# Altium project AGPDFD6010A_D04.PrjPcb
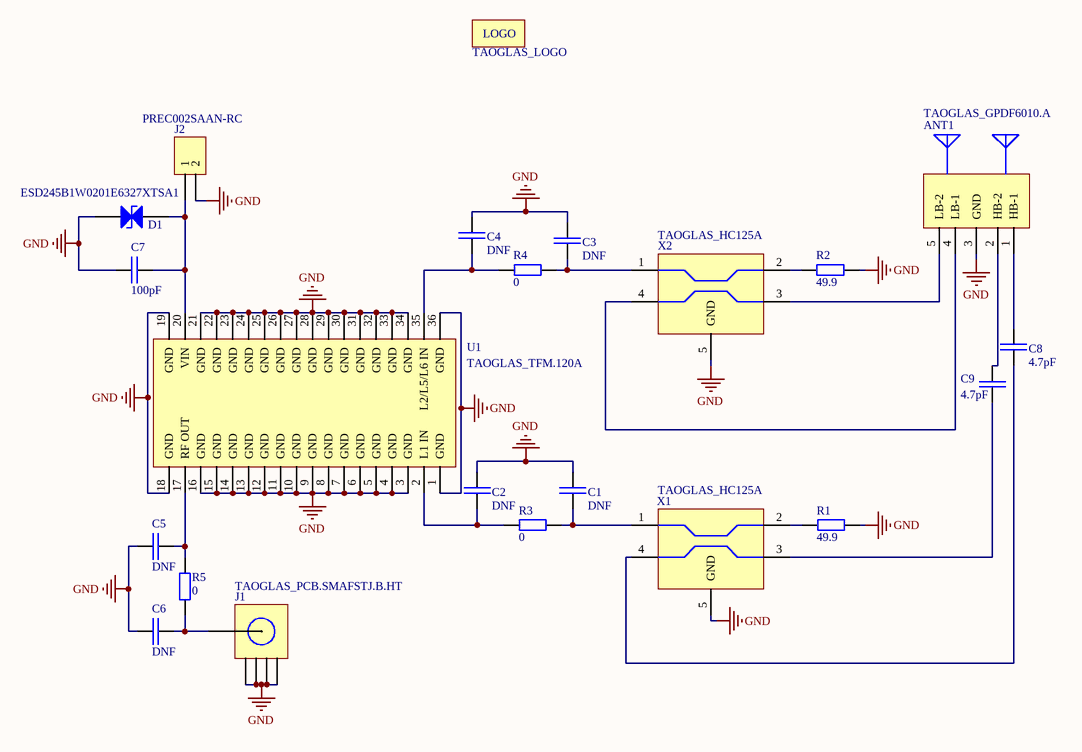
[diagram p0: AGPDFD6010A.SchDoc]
1 sheet, 22 parts. Net scope: global (net labels, ports and power ports of the same name join across sheets).
Board file: AGPDFD6010A_D04.PcbDoc

## Sheet AGPDFD6010A.SchDoc
size Tabloid; SheetNumber: 1; SheetTotal: 1; ProjName: AGPDFD6010A_D04.PrjPcb

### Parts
ANT1  TAOGLAS_GPDF6010.A  [TAOGLAS_GPDF6010.A]
C1  DNF  [0402 - DNF]
C2  DNF  [0402 - DNF]
C3  DNF  [0402 - DNF]
C4  DNF  [0402 - DNF]
C5  DNF  [0402 - DNF]
C6  DNF  [0402 - DNF]
C7  100pF  [Capacitor - 0402 - GRM]
C8  4.7pF  [Capacitor - 0402 - GRM]
C9  4.7pF  [Capacitor - 0402 - GRM]
D1  ESD245B1W0201E6327XTSA1  [Diode - 0201 (0603 Metric) - DSN0603-2]
J1  TAOGLAS_PCB.SMAFSTJ.B.HT  [TAOGLAS_PCB.SMAFSTJ.B.HT]
J2  PREC002SAAN-RC  [SULLINS_PREC002SAAN-RC]
LOGO*1  TAOGLAS_LOGO  [TAOGLAS_LOGO - No R - 10.3mm]  (no BOM)
R1  value 49.9  [Resistor - 0402 - RC_L]  (hidden comment: Resistor_Thick Film_1005(0402)_49.9Ohms+-1%_0.063W)
R2  value 49.9  [Resistor - 0402 - RC_L]  (hidden comment: Resistor_Thick Film_1005(0402)_49.9Ohms+-1%_0.063W)
R3  value 0  [Resistor - 0402 - RC_L]  (hidden comment: Resistor_Thick Film_1005(0402)_0Ohm)
R4  value 0  [Resistor - 0402 - RC_L]  (hidden comment: Resistor_Thick Film_1005(0402)_0Ohm)
R5  value 0  [Resistor - 0402 - RC_L]  (hidden comment: Resistor_Thick Film_1005(0402)_0Ohm)
U1  TAOGLAS_TFM.120A  [TAOGLAS_TFM.120A]
X1  TAOGLAS_HC125A  [TAOGLAS_HC125A]
X2  TAOGLAS_HC125A  [TAOGLAS_HC125A]

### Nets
GND: ANT1.3(GND) C1.2 C2.2 C3.2 C4.2 C5.1 C6.2 C7.1 D1.2(ANODE) J1.2(GND) J1.3(GND) J1.4(GND) J1.5(GND) J2.2 R1.2 R2.2 U1.1(GND) U1.3(GND) U1.4(GND) U1.5(GND) U1.6(GND) U1.7(GND) U1.8(GND) U1.9(GND) U1.10(GND) U1.11(GND) U1.12(GND) U1.13(GND) U1.14(GND) U1.15(GND) U1.16(GND) U1.18(GND) U1.19(GND) U1.21(GND) U1.22(GND) U1.23(GND) U1.24(GND) U1.25(GND) U1.26(GND) U1.27(GND) U1.28(GND) U1.29(GND) U1.30(GND) U1.31(GND) U1.32(GND) U1.33(GND) U1.34(GND) U1.36(GND) X1.5(GND) X2.5(GND)
NetANT1_1: ANT1.1(HB-1) C8.2
NetANT1_2: ANT1.2(HB-2) C9.2
NetANT1_4: ANT1.4(LB-1) X2.4
NetANT1_5: ANT1.5(LB-2) X2.3
NetC1_1: C1.1 R3.2 X1.1
NetC2_1: C2.1 R3.1 U1.2(L1_IN)
NetC3_1: C3.1 R4.2 X2.1
NetC4_1: C4.1 R4.1 U1.35(L2/L5/L6_IN)
NetC5_2: C5.2 R5.1 U1.17(RF_OUT)
NetC6_1: C6.1 J1.1 R5.2
NetC7_2: C7.2 D1.1(CATHODE) J2.1 U1.20(VIN)
NetC8_1: C8.1 X1.4
NetC9_1: C9.1 X1.3
NetR1_1: R1.1 X1.2
NetR2_1: R2.1 X2.2

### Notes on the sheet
- Labels drawn without touching a wire or pin: GND

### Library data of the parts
ANT1 = CMP-519-000000-4: Passive All-band High Precision GNSS Stacked Dual Pin Dual Feed Patch Antenna; Temp_Low: -40C; Temp_High: +85C; ComponentLibStatus: Created
C1-C6 = CMP-00006-25: Do Not Fit
C7 = CMP-001-00343-45: 100 pF ±5% 50V Ceramic Capacitor C0G, NP0 0402 (1005 Metric); MFG: Murata Electronics; MFGPN: GRM1555C1H101JA01D; Product Status: Not For New Designs
C8 C9 = CMP-001-00399-44: 4.7 pF ±0.25pF 50V Ceramic Capacitor C0G, NP0 0402 (1005 Metric); MFGPN: GRM1555C1H4R7CA01D; MFG: Murata Electronics; Product Status: Not For New Designs
D1 = CMP-004-00167-10: 7.5V Clamp 5.5A (8/20µs) Ipp Tvs Diode Surface Mount WLL-2-3; MFG: Infineon Technologies; Type: Zener; Voltage - Reverse Standoff (Typ): 5.5V; Capacitance @ Frequency: 5.8pF @ 1GHz; Power Line Protection: No; Base Product Number: ESD245; Bidirectional Channels: 1; Power - Peak Pulse: 44W
J1 = CMP-028-000009-10: SMA (F) Surface Mount PCB Jack; ComponentLibStatus: Created; Temp_Low: -40C; Temp_High: +85C
J2 = CMP-002-00180-7: Connector Header Through Hole 2 position 0.100" (2.54mm); MFG: Sullins Connector Solutions; Product Status: Active; Connector Type: BOARD CONNECTOR; Number of Positions: 2; Temp_High: 105°C; Temp_Low: -40°C; Angle: 180°
LOGO*1 = CMP-048-000000-3: Silkscreen Logo - Standard
R1 R2 = CMP-009-00330-4: 49.9 Ohms ±1% 0.1W, 1/10W Chip Resistor 0402 (1005 Metric) Automotive AEC-Q200 Thick Film; Temperature Coefficient: ±100ppm/°C; Product Status: Active; MFG: YAGEO; MFGPN: RC0402FR-0749R9L; Power (Watts): 63mW
R3-R5 = CMP-009-00375-4: 0 Ohms Jumper Chip Resistor 0402 (1005 Metric) Moisture Resistant Thick Film; MFG: YAGEO; Product Status: Active; MFGPN: RC0402JR-070RL
U1 = CMP-272-000001-5: Surface mount GNSS front-end module covering L1+B1+G1/L2/L5+L-band; Temp_High: +85C; Temp_Low: -40C; ComponentLibStatus: Created
X1 X2 = CMP-002-000151-19: Low Profile, High Performance Multiband GNSS Hybrid Coupler; Product Status: Active; Center Frequency: 1.39GHz; MFGPN: HC125A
